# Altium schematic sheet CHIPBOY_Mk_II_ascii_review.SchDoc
size A; SheetNumber: 1; SheetTotal: 1
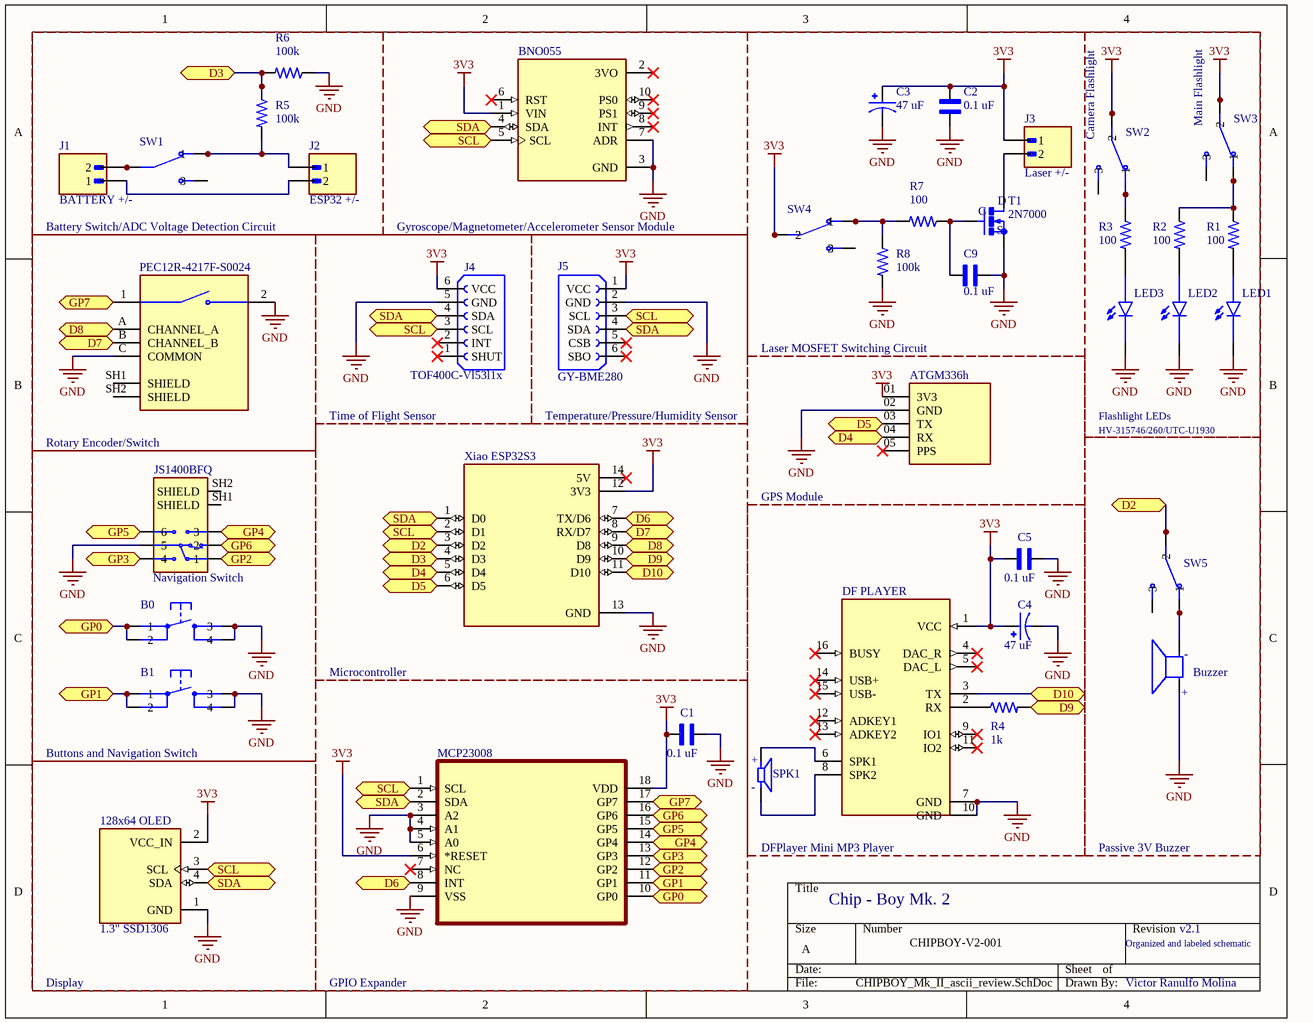
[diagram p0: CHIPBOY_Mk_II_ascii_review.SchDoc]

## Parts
128x64_OLED  1.3" SSD1306  [MODULE_DM-OLED096-636]
ATGM336h  ATGM336H  [SAMTEC_MTSW-105-07-L-S-240-LL]  (value not drawn)
B0  SKHHANA010  [SW_SKHHANA010]  (value not drawn)
B1  SKHHANA010  [SW_SKHHANA010]  (value not drawn)
BNO055  BNO055  [MODULE_2472]  (value not drawn)
Buzzer  (no value)  [CUI_CMI-1295IC-0385T]
C1  0.1 uF  [CAPRB250W50L450T300H550]
C2  0.1 uF  [CAPRB250W50L450T300H550]
C3  47 uF  [CAP_EEETPV470XAV]
C4  47 uF  [CAP_EEETPV470XAV]
C5  0.1 uF  [CAPRB250W50L450T300H550]
C9  0.1 uF  [CAPRB250W50L450T300H550]
DF_PLAYER  DFPLAYER  [MODULE_DFR0299]  (value not drawn)
GY-BME280  J5  [SULLINS_PPTC061LFBN-RC]
J1  BATTERY +/-  [HARWIN_M20-9990246]
J2  ESP32 +/-  [HARWIN_M20-9990246]
J3  Laser +/-  [HARWIN_M20-9990246]
LED1  led_through_hole  [LED_WP7113ID]  (value not drawn)
LED2  led_through_hole  [LED_WP7113ID]  (value not drawn)
LED3  led_through_hole  [LED_WP7113ID]  (value not drawn)
MCP23008  gpio extender  [DIP254P762X533-18]  (value not drawn)
Navigation_Switch  JS1400BFQ  [SW_JS1400BFQ]
PEC12R-4217F-S0024  rotary encoder  [XDCR_PEC12R-4217F-S0024]  (value not drawn)
R1  100  [RESAD640W45L370D200]
R2  100  [RESAD640W45L370D200]
R3  100  [RESAD640W45L370D200]
R4  1k  [RESAD640W45L370D200]
R5  100k  [RESAD640W45L370D200]
R6  100k  [RESAD640W45L370D200]
R7  100  [RESAD640W45L370D200]
R8  100k  [RESAD640W45L370D200]
SPK1  15mm speaker  [SPKR_CVS-1508]  (value not drawn)
SW1  switch top actuated  [SW_MHSS1104]  (value not drawn)
SW2  Camera Flashlight  [SW_MHSS1104]
SW3  Main Flashlight  [SW_MHSS1104]
SW4  switch top actuated  [SW_MHSS1104]  (value not drawn)
SW5  switch top actuated  [SW_MHSS1104]  (value not drawn)
T1  2N7000  [TO92]
TOF400C-Vl53l1x  J4  [SULLINS_PPTC061LFBN-RC]
Xiao_ESP32S3  (no value)  [MODULE_113991254]

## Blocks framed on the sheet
Battery Switch/ADC Voltage Detection Circuit: J1 J2 R5 R6 SW1
Gyroscope/Magnetometer/Accelerometer Sensor Module: BNO055
Laser MOSFET Switching Circuit: C2 C3 C9 J3 R7 R8 SW4 T1
Flashlight LEDs: LED1-LED3 R1-R3 SW2 SW3
Temperature/Pressure/Humidity Sensor: GY-BME280
Passive 3V Buzzer: Buzzer SW5

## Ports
D2 (bidir, see CHIPBOY_Mk_II[2C]), D2 (bidir, see CHIPBOY_Mk_II[4B]), D3 (bidir, see CHIPBOY_Mk_II[1A]), D3 (bidir, see CHIPBOY_Mk_II[2C]), D4 (bidir, see CHIPBOY_Mk_II[2C]), D4 (bidir, see CHIPBOY_Mk_II[3B]), D5 (bidir, see CHIPBOY_Mk_II[2C]), D5 (bidir, see CHIPBOY_Mk_II[3B]), D6 (bidir, see CHIPBOY_Mk_II[2C]), D6 (bidir, see CHIPBOY_Mk_II[2D]), D7 (bidir, see CHIPBOY_Mk_II[1B]), D7 (bidir, see CHIPBOY_Mk_II[2C]), D8 (bidir, see CHIPBOY_Mk_II[1B]), D8 (bidir, see CHIPBOY_Mk_II[2C]), D9 (bidir, see CHIPBOY_Mk_II[2C]), D9 (bidir, see CHIPBOY_Mk_II[4C]), D10 (bidir, see CHIPBOY_Mk_II[2C]), D10 (bidir, see CHIPBOY_Mk_II[4C]), GP0 (bidir, see CHIPBOY_Mk_II[1C]), GP0 (bidir, see CHIPBOY_Mk_II[3D]), GP1 (bidir, see CHIPBOY_Mk_II[1C]), GP1 (bidir, see CHIPBOY_Mk_II[3D]), GP2 (bidir, see CHIPBOY_Mk_II[1C]), GP2 (bidir, see CHIPBOY_Mk_II[3D]), GP3 (bidir, see CHIPBOY_Mk_II[1C]), GP3 (bidir, see CHIPBOY_Mk_II[3D]), GP4 (bidir, see CHIPBOY_Mk_II[1C]), GP4 (bidir, see CHIPBOY_Mk_II[3D]), GP5 (bidir, see CHIPBOY_Mk_II[1C]), GP5 (bidir, see CHIPBOY_Mk_II[3D]), GP6 (bidir, see CHIPBOY_Mk_II[1C]), GP6 (bidir, see CHIPBOY_Mk_II[3D]), GP7 (bidir, see CHIPBOY_Mk_II[1B]), GP7 (bidir, see CHIPBOY_Mk_II[3D]), SCL (bidir, see CHIPBOY_Mk_II[1D], CHIPBOY_Mk_II[2A], CHIPBOY_Mk_II[2B], CHIPBOY_Mk_II[2C]), SCL (bidir, see CHIPBOY_Mk_II[1D], CHIPBOY_Mk_II[2A], CHIPBOY_Mk_II[2B], CHIPBOY_Mk_II[2C], CHIPBOY_Mk_II[2D]), SCL (bidir, see CHIPBOY_Mk_II[1D], CHIPBOY_Mk_II[2A], CHIPBOY_Mk_II[2B], CHIPBOY_Mk_II[2D]), SCL (bidir, see CHIPBOY_Mk_II[1D], CHIPBOY_Mk_II[2B], CHIPBOY_Mk_II[2C], CHIPBOY_Mk_II[2D]), SCL (bidir, see CHIPBOY_Mk_II[2A], CHIPBOY_Mk_II[2B], CHIPBOY_Mk_II[2C], CHIPBOY_Mk_II[2D]), SDA (bidir, see CHIPBOY_Mk_II[1D], CHIPBOY_Mk_II[2A], CHIPBOY_Mk_II[2B], CHIPBOY_Mk_II[2C]), SDA (bidir, see CHIPBOY_Mk_II[1D], CHIPBOY_Mk_II[2A], CHIPBOY_Mk_II[2B], CHIPBOY_Mk_II[2C], CHIPBOY_Mk_II[2D]), SDA (bidir, see CHIPBOY_Mk_II[1D], CHIPBOY_Mk_II[2A], CHIPBOY_Mk_II[2B], CHIPBOY_Mk_II[2D]), SDA (bidir, see CHIPBOY_Mk_II[1D], CHIPBOY_Mk_II[2B], CHIPBOY_Mk_II[2C], CHIPBOY_Mk_II[2D]), SDA (bidir, see CHIPBOY_Mk_II[2A], CHIPBOY_Mk_II[2B], CHIPBOY_Mk_II[2C], CHIPBOY_Mk_II[2D])

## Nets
3V3: 128x64_OLED.2(VCC_IN) ATGM336h.01(3V3) BNO055.1(VIN) C1.1 C2.1 C3.1 C4.1 C5.1 DF_PLAYER.1(VCC) GY-BME280.1(VCC) J3.1 MCP23008.6(*RESET) MCP23008.18(VDD) SW2.3(2) SW2.4 SW3.3(2) SW3.4 SW4.3(2) SW4.4(2) TOF400C-Vl53l1x.6(VCC) Xiao_ESP32S3.12(3V3)
GND: 128x64_OLED.1(GND) ATGM336h.02(GND) B0.3 B0.4 B1.3 B1.4 BNO055.3(GND) BNO055.7(ADR) Buzzer.P C1.2 C2.2 C3.2 C4.2 C5.2 C9.1 DF_PLAYER.7(GND) DF_PLAYER.10(GND) GY-BME280.2(GND) LED1.C LED2.C LED3.C MCP23008.3(A2) MCP23008.4(A1) MCP23008.5(A0) MCP23008.9(VSS) Navigation_Switch.5 PEC12R-4217F-S0024.2 PEC12R-4217F-S0024.C(COMMON) R6.1 R8.2 T1.3(S) TOF400C-Vl53l1x.5(GND) Xiao_ESP32S3.13(GND)
D2: SW5.3(2) SW5.4 Xiao_ESP32S3.3(D2) ; port D2
D3: R5.1 R6.2 Xiao_ESP32S3.4(D3) ; port D3
D4: ATGM336h.04(RX) Xiao_ESP32S3.5(D4) ; port D4
D5: ATGM336h.03(TX) Xiao_ESP32S3.6(D5) ; port D5
D6: MCP23008.8(INT) Xiao_ESP32S3.7(TX/D6) ; port D6
D7: PEC12R-4217F-S0024.B(CHANNEL_B) Xiao_ESP32S3.8(RX/D7) ; port D7
D8: PEC12R-4217F-S0024.A(CHANNEL_A) Xiao_ESP32S3.9(D8) ; port D8
D9: R4.2 Xiao_ESP32S3.10(D9) ; port D9
D10: DF_PLAYER.3(TX) Xiao_ESP32S3.11(D10) ; port D10
GP0: B0.1 B0.2 MCP23008.10(GP0) ; port GP0
GP1: B1.1 B1.2 MCP23008.11(GP1) ; port GP1
GP2: MCP23008.12(GP2) Navigation_Switch.1 ; port GP2
GP3: MCP23008.13(GP3) Navigation_Switch.4 ; port GP3
GP4: MCP23008.14(GP4) Navigation_Switch.3 ; port GP4
GP5: MCP23008.15(GP5) Navigation_Switch.6 ; port GP5
GP6: MCP23008.16(GP6) Navigation_Switch.2 ; port GP6
GP7: MCP23008.17(GP7) PEC12R-4217F-S0024.1 ; port GP7
SCL: 128x64_OLED.3(SCL) BNO055.5(SCL) GY-BME280.3(SCL) MCP23008.1(SCL) TOF400C-Vl53l1x.3(SCL) Xiao_ESP32S3.2(D1) ; port SCL
SDA: 128x64_OLED.4(SDA) BNO055.4(SDA) GY-BME280.4(SDA) MCP23008.2(SDA) TOF400C-Vl53l1x.4(SDA) Xiao_ESP32S3.1(D0) ; port SDA
NetBuzzer_N: Buzzer.N SW5.1 SW5.2
NetC9_2: C9.2 R7.1 T1.2(G)
NetDF_PLAYER_2: DF_PLAYER.2(RX) R4.1
NetDF_PLAYER_6: DF_PLAYER.6(SPK1) SPK1.P
NetDF_PLAYER_8: DF_PLAYER.8(SPK2) SPK1.M
NetJ1_1: J1.1 J2.2
NetJ1_2: J1.2 SW1.3 SW1.4
NetJ2_1: J2.1 R5.2 SW1.1 SW1.2
NetJ3_2: J3.2 T1.1(D)
NetLED1_A: LED1.A R1.2
NetLED2_A: LED2.A R2.2
NetLED3_A: LED3.A R3.2
NetR1_1: R1.1 R2.1 SW3.1 SW3.2
NetR3_1: R3.1 SW2.1 SW2.2
NetR7_2: R7.2 R8.1 SW4.1 SW4.2(1)
NetSW1_5: SW1.5(3) SW1.6
NetSW2_5: SW2.5(3) SW2.6
NetSW3_5: SW3.5(3) SW3.6
NetSW4_5: SW4.5(3) SW4.6(3)
NetSW5_5: SW5.5(3) SW5.6

Not connected (* = marked no-connect by the designer): ATGM336h 05(PPS)*; BNO055 2(3VO)* 6(RST)* 8(INT)* 9(PS1)* 10(PS0)*; DF_PLAYER 4(DAC_R)* 5(DAC_L)* 9(IO1)* 11(IO2)* 12(ADKEY1)* 13(ADKEY2)* 14(USB+)* 15(USB-)* 16(BUSY)*; GY-BME280 5(CSB)* 6(SBO)*; MCP23008 7(NC)*; Navigation_Switch SH1(SHIELD) SH2(SHIELD); PEC12R-4217F-S0024 SH1(SHIELD) SH2(SHIELD); TOF400C-Vl53l1x 1(SHUT)* 2(INT)*; Xiao_ESP32S3 14(5V)*

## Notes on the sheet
- Time of Flight Sensor
- HV-315746/260/UTC-U1930
- Rotary Encoder/Switch
- GPS Module
- Microcontroller
- (near B1) Buttons and Navigation Switch
- (near DF_PLAYER) DFPlayer Mini MP3 Player
- Chip - Boy Mk. 2
- CHIPBOY-V2-001
- Organized and labeled schematic
- v2.1
- Display
- GPIO Expander
- Victor Ranulfo Molina

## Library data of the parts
128x64_OLED = DM-OLED096-636
ATGM336h = 5 pin header
Buzzer = Buzzer_3V
C1 C2 C5 C9 = 0_1uF100V_CAP_FA14X7R2A104KNU00
C3 C4 = 47uF_SMD
GY-BME280 TOF400C-Vl53l1x = PPTC061LFBNRC
J1-J3 = 2_pin_header
Navigation_Switch = nav switch
R1-R8 = resistor_through_hole
SW2 SW3 = switch top actuated
T1 = mosfet
Xiao_ESP32S3 = xiao_esp32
